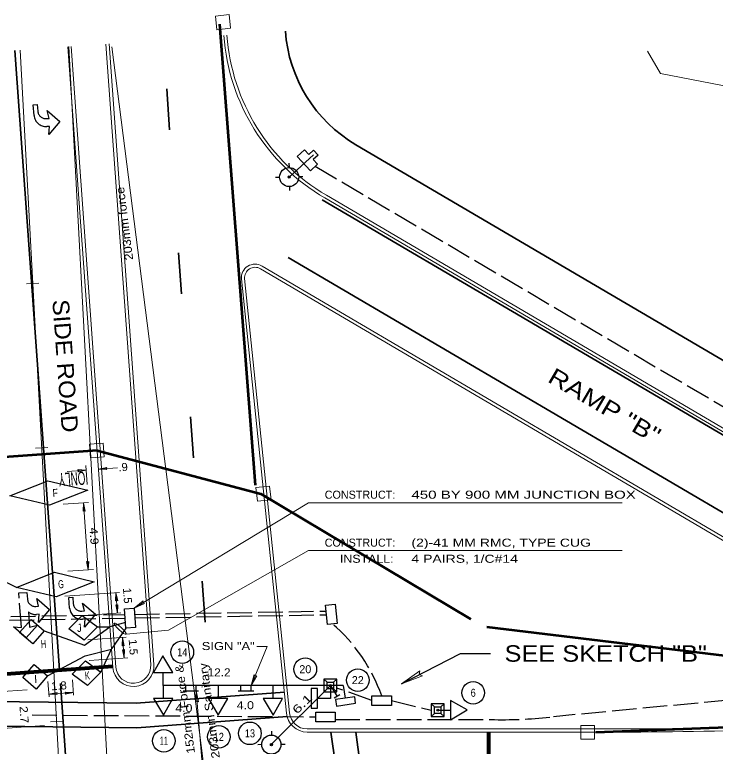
# Model space of a CAD drawing. Extents: x 168203 to 169864, y 223196 to 223870.
# Drawn here: x 168345.6 to 168396.8, y 223652.4 to 223705.8 of the extents above; entities that cross this region are included whole.
import ezdxf
from ezdxf.enums import TextEntityAlignment as Align

# ---------------------------------------------------------------- set-up
doc = ezdxf.new("R2010")
doc.units = 0
doc.header["$LTSCALE"] = 0.3
doc.header["$PDMODE"] = 32
doc.header["$PDSIZE"] = 0.15
doc.linetypes.add('LONG_DASH_SHORT_DASH', pattern=[9.9, 6, -1.2, 1.5, -1.2])
doc.linetypes.add('LONG_DASHED', pattern=[7.5, 6, -1.5])
for name, color, linetype, lineweight in [('1', 7, 'Continuous', 13), ('10', 7, 'Continuous', 13), ('23', 7, 'Continuous', 25), ('32', 7, 'Continuous', 25), ('36', 7, 'Continuous', 35), ('4', 7, 'Continuous', 25), ('6', 7, 'Continuous', 25), ('8', 7, 'Continuous', 25)]:
    doc.layers.add(name, color=color, linetype=linetype, lineweight=lineweight)

msp = doc.modelspace()

# ---------------------------------------------------------------- linework, layer by layer
at = {"layer": '1'}
for p, q in [((168349.7975, 223634.2675), (168346.0287, 223703.2124)), ((168352.8001, 223658.1888), (168349.528, 223703.4653)), ((168353.0296, 223658.2052), (168349.7575, 223703.4819)), ((168352.2908, 223703.665), (168355.5629, 223658.3883)), ((168352.5202, 223703.6815), (168355.7923, 223658.4049)), ((168417.1498, 223663.9927), (168368.3802, 223692.6319)), ((168417.0333, 223663.7944), (168368.2637, 223692.4336)), ((168363.5687, 223687.27), (168399.2919, 223666.2921)), ((168363.6851, 223687.4684), (168399.4139, 223666.4872)), ((168346.5111, 223686.1736), (168347.4098, 223686.2226)), ((168365.473, 223654.8595), (168362.1813, 223686.534)), ((168365.7018, 223654.8832), (168362.4101, 223686.5577)), ((168347.1644, 223674.1914), (168348.0631, 223674.2404)), ((168348.256, 223654.2212), (168349.1547, 223654.2702)), ((168389.7958, 223653.6976), (168366.9691, 223653.6976)), ((168389.7958, 223653.4676), (168366.9691, 223653.4676))]:
    msp.add_line(p, q, dxfattribs=at)
at = {"layer": '1', "lineweight": 35}
msp.add_line((168419.4337, 223667.6033), (168370.5425, 223696.3139), dxfattribs=at)
at = {"layer": '1'}
for points in [[(168360.2873, 223705.7061), (168361.2849, 223705.8098), (168361.3886, 223704.8122), (168360.391, 223704.7085)], [(168351.1029, 223674.483), (168352.1033, 223674.5553), (168352.1756, 223673.5549), (168351.1752, 223673.4826)], [(168363.2438, 223671.3005), (168364.2414, 223671.4042), (168364.3451, 223670.4066), (168363.3475, 223670.3029)], [(168386.9482, 223652.949), (168386.9482, 223653.952), (168387.9512, 223653.952), (168387.9512, 223652.949)]]:
    msp.add_lwpolyline(points, close=True, dxfattribs=at)
for centre, radius, start, end in [((168375.8594, 223705.3683), 15, 184.13349, 239.57703), ((168375.8594, 223705.3683), 14.77, 184.13349, 239.57703), ((168363.1787, 223686.6061), 1, 59.57703, 184.13349), ((168363.1787, 223686.6061), 0.77, 59.57703, 184.13349), ((168354.296, 223658.2969), 1.5, 184.13349, 4.13349), ((168354.296, 223658.2969), 1.27, 184.13349, 4.13349), ((168366.9691, 223654.9676), 1.5, 184.13349, 270.00005), ((168366.9691, 223654.9676), 1.27, 184.13349, 270.00005), ((168389.7956, 223953.4676), 299.77, 270.00005, 274.68735), ((168389.7956, 223953.4676), 300, 270.00005, 274.68735)]:
    msp.add_arc(centre, radius, start, end, dxfattribs=at)
at = {"layer": '1', "lineweight": 35}
msp.add_arc((168375.8594, 223705.3683), 10.5001, 184.13349, 239.57769, dxfattribs=at)
at = {"layer": '10'}
for p, q in [((168354.3616, 223662.5186), (168367.0853, 223670.2051)), ((168389.9644, 223670.2051), (168367.0853, 223670.2051)), ((168389.9644, 223666.7051), (168367.0853, 223666.7051))]:
    msp.add_line(p, q, dxfattribs=at)
at = {"layer": '10', "lineweight": 25}
for p, q in [((168373.8561, 223656.997), (168378.1708, 223659.2014)), ((168378.1708, 223659.2014), (168380.368, 223659.2014))]:
    msp.add_line(p, q, dxfattribs=at)
at = {"layer": '10'}
msp.add_lwpolyline([(168353.7695, 223660.6006), (168356.8513, 223660.8997), (168367.0853, 223666.7051)], dxfattribs=at)
for points in [[(168355.1091, 223662.8541), (168354.3616, 223662.5186), (168355.0017, 223663.0319), (168354.9881, 223662.8971)], [(168375.3951, 223657.56), (168373.8561, 223656.997), (168375.2059, 223657.9302), (168375.1597, 223657.663)]]:
    msp.add_lwpolyline(points, close=True, dxfattribs=at)
msp.add_ellipse((168353.3324, 223661.0127), major_axis=(-0.4371, 0.4121), ratio=0.187826, dxfattribs=at)
at = {"layer": '23', "lineweight": 53}
for p, q in [((168363.2123, 223671.494), (168360.5984, 223705.115)), ((168351.6566, 223674.0176), (168339.6878, 223673.1527)), ((168351.6566, 223674.0176), (168363.59, 223670.8389)), ((168363.59, 223670.8389), (168378.9117, 223661.7152)), ((168380.0972, 223661.1384), (168422.0981, 223656.1092)), ((168388.052, 223653.4671), (168412.6271, 223654.3671))]:
    msp.add_line(p, q, dxfattribs=at)
at = {"layer": '23', "lineweight": 13}
for p, q in [((168357.586, 223554.132), (168349.5897, 223703.4835)), ((168359.4003, 223651.3453), (168352.7333, 223703.4586))]:
    msp.add_line(p, q, dxfattribs=at)
msp.add_lwpolyline([(168391.8032, 223703.15), (168392.7497, 223701.5053), (168408.4668, 223698.4649)], dxfattribs=at)
at = {"layer": '32'}
for p, q in [((168367.4388, 223695.578), (168365.6659, 223693.9605)), ((168356.4781, 223656.8676), (168356.4781, 223657.8074)), ((168368.6781, 223656.8676), (168356.4781, 223656.8676)), ((168356.4781, 223656.8676), (168356.4781, 223655.9278)), ((168358.1165, 223656.4839), (168358.1165, 223656.8634)), ((168358.8755, 223656.4839), (168358.8755, 223656.8634)), ((168360.4781, 223656.8676), (168360.4781, 223655.9278)), ((168362.1365, 223656.4888), (168362.1365, 223656.8683)), ((168362.8955, 223656.4888), (168362.8955, 223656.8683)), ((168368.6781, 223656.8676), (168364.3648, 223652.5542)), ((168364.4781, 223656.8676), (168364.4781, 223655.9278)), ((168368.6781, 223656.8676), (168368.6781, 223655.9278)), ((168369.6179, 223656.8676), (168368.6781, 223656.8676)), ((168368.6781, 223656.8676), (168369.1665, 223656.0647)), ((168369.6179, 223656.8676), (168369.7512, 223655.9373)), ((168357.9267, 223656.4839), (168359.0562, 223656.4839)), ((168361.9467, 223656.4888), (168363.0762, 223656.4888)), ((168368.6781, 223655.9278), (168367.7383, 223655.9278)), ((168369.3672, 223656.1867), (168368.958, 223655.9379)), ((168376.5061, 223655.0676), (168377.4459, 223655.0676))]:
    msp.add_line(p, q, dxfattribs=at)
at = {"layer": '32', "lineweight": 13}
for p in [(168362.8955, 223656.8683), (168363.3021, 223659.7147)]:
    msp.add_line(p, (168364.0608, 223659.7147), dxfattribs=at)
at = {"layer": '32'}
for points in [[(168356.46, 223659.0272), (168355.7733, 223657.8074), (168356.4781, 223657.8074), (168357.1829, 223657.8074)], [(168367.2685, 223656.6417), (168367.2685, 223655.223), (168367.7383, 223655.223), (168367.7383, 223656.6417)], [(168356.4962, 223654.708), (168357.1829, 223655.9278), (168356.4781, 223655.9278), (168355.7733, 223655.9278)], [(168360.4962, 223654.708), (168361.1829, 223655.9278), (168360.4781, 223655.9278), (168359.7733, 223655.9278)], [(168364.4962, 223654.708), (168365.1829, 223655.9278), (168364.4781, 223655.9278), (168363.7733, 223655.9278)], [(168369.1112, 223655.371), (168370.5155, 223655.5722), (168370.4489, 223656.0373), (168369.0445, 223655.836)], [(168378.6657, 223655.0857), (168377.4459, 223655.7724), (168377.4459, 223655.0676), (168377.4459, 223654.3628)]]:
    msp.add_lwpolyline(points, close=True, dxfattribs=at)
at = {"layer": '32', "lineweight": 13}
for points in [[(168363.2956, 223657.5833), (168362.8955, 223656.8683), (168363.1033, 223657.662), (168363.1728, 223657.5456)], [(168358.8429, 223655.6652), (168358.8755, 223656.4839), (168359.05, 223655.6822), (168358.9353, 223655.7544)]]:
    msp.add_lwpolyline(points, close=True, dxfattribs=at)
msp.add_lwpolyline([(168358.5538, 223651.1547), (168359.3125, 223651.1547), (168358.8755, 223656.4839)], dxfattribs=at)
at = {"layer": '32'}
for centre in [(168357.8675, 223659.2956), (168366.8425, 223658.0542), (168370.6726, 223657.2577), (168379.0954, 223656.3366), (168362.8039, 223653.376), (168356.52, 223652.8356), (168360.5298, 223653.1218)]:
    msp.add_circle(centre, 0.8236, dxfattribs=at)
at = {"layer": '36'}
for p, q in [((168348.9037, 223658.0067), (168345.6389, 223703.1842)), ((168356.7281, 223700.3938), (168356.9443, 223697.4016)), ((168368.071, 223692.3059), (168402.7689, 223671.93)), ((168357.5931, 223688.425), (168357.8093, 223685.4328)), ((168365.5999, 223688.0978), (168400.2978, 223667.7219)), ((168358.4581, 223676.4562), (168358.6743, 223673.464)), ((168359.323, 223664.4874), (168359.5393, 223661.4952)), ((168349.5082, 223649.6433), (168348.9759, 223657.0092)), ((168354.5482, 223653.7832), (168365.5163, 223654.5943)), ((168331.8751, 223654.0405), (168354.5482, 223653.7832)), ((168374.0279, 223615.7265), (168368.7066, 223653.4676)), ((168375.8367, 223615.7899), (168370.5243, 223653.4676))]:
    msp.add_line(p, q, dxfattribs=at)
at = {"layer": '36', "lineweight": 80}
for p, q in [((168336.8478, 223657.135), (168352.7935, 223658.2879)), ((168380.2469, 223634.5676), (168380.2468, 223653.4676))]:
    msp.add_line(p, q, dxfattribs=at)
at = {"layer": '36', "linetype": 'LONG_DASH_SHORT_DASH', "lineweight": 25}
for points in [[(168347.0511, 223698.4569), (168346.9949, 223699.2352), (168347.2867, 223699.2563), (168347.3219, 223698.7699)], [(168347.9477, 223698.2284), (168348.1423, 223698.2425), (168348.0029, 223698.8191), (168348.9417, 223698.0069), (168348.1295, 223697.0681), (168348.1845, 223697.6588), (168347.9899, 223697.6447)], [(168346.635, 223662.2303), (168346.7145, 223661.1318), (168347.2911, 223661.2712), (168346.4789, 223660.3324), (168345.5401, 223661.1446), (168346.1308, 223661.0896), (168345.9479, 223663.6189), (168346.5316, 223663.6611), (168346.5668, 223663.1746)], [(168347.1926, 223662.6332), (168347.3872, 223662.6472), (168347.2478, 223663.2239)], [(168347.2478, 223663.2239), (168348.1866, 223662.4117), (168347.3744, 223661.4728), (168347.4294, 223662.0636), (168347.2348, 223662.0495)], [(168349.6464, 223662.519), (168349.5902, 223663.2973), (168349.882, 223663.3184), (168349.9172, 223662.832)], [(168350.543, 223662.2905), (168350.7376, 223662.3046), (168350.5982, 223662.8812), (168351.537, 223662.069), (168350.7248, 223661.1302), (168350.7798, 223661.7209), (168350.5852, 223661.7068)]]:
    msp.add_lwpolyline(points, dxfattribs=at)
at = {"layer": '36'}
msp.add_lwpolyline([(168335.3225, 223655.8015), (168354.4921, 223655.584), (168365.3145, 223656.3843)], dxfattribs=at)
at = {"layer": '36', "linetype": 'LONG_DASH_SHORT_DASH', "lineweight": 25}
for centre, radius, start in [((168347.9267, 223698.5203), 0.8778, 184.13538), ((168347.9056, 223698.8121), 0.5852, 184.13538), ((168347.1505, 223663.2169), 0.5852, 184.13538), ((168350.5009, 223662.8742), 0.5852, 184.13538), ((168347.1716, 223662.925), 0.8778, 232.32592), ((168350.522, 223662.5824), 0.8778, 184.13538)]:
    msp.add_arc(centre, radius, start, 274.13538, dxfattribs=at)
at = {"layer": '4'}
for p, q in [((168368.2037, 223657.3375), (168368.4387, 223657.1025)), ((168369.1435, 223657.3375), (168368.9085, 223657.1025)), ((168368.2037, 223656.3977), (168368.4387, 223656.6327)), ((168369.1435, 223656.3977), (168368.9085, 223656.6327)), ((168376.0317, 223655.5375), (168376.2667, 223655.3025)), ((168376.9715, 223655.5375), (168376.7365, 223655.3025)), ((168376.0317, 223654.5977), (168376.2667, 223654.8327)), ((168376.9715, 223654.5977), (168376.7365, 223654.8327))]:
    msp.add_line(p, q, dxfattribs=at)
for points in [[(168368.2037, 223657.3375), (168368.2037, 223656.3977), (168369.1435, 223656.3977), (168369.1435, 223657.3375)], [(168368.4387, 223657.1025), (168368.9085, 223657.1025), (168368.9085, 223656.6327), (168368.4387, 223656.6327)], [(168376.0317, 223655.5375), (168376.0317, 223654.5977), (168376.9715, 223654.5977), (168376.9715, 223655.5375)], [(168376.2667, 223655.3025), (168376.7365, 223655.3025), (168376.7365, 223654.8327), (168376.2667, 223654.8327)]]:
    msp.add_lwpolyline(points, close=True, dxfattribs=at)
for p in [(168368.6826, 223656.8676), (168376.5106, 223655.0676)]:
    msp.add_point(p, dxfattribs=at)
at = {"layer": '6', "linetype": 'LONG_DASHED'}
for p, q in [((168367.5642, 223694.7428), (168407.4794, 223671.2335)), ((168354.395, 223662.0561), (168368.3631, 223662.2946)), ((168338.522, 223661.5206), (168353.6992, 223661.7798)), ((168338.6143, 223661.7866), (168353.6802, 223662.0439)), ((168354.4141, 223661.7921), (168368.3905, 223662.0308)), ((168353.7213, 223661.474), (168352.5856, 223661.1565)), ((168353.7518, 223661.0521), (168352.7043, 223659.5146)), ((168371.7071, 223655.7676), (168369.1435, 223656.6774)), ((168406.6999, 223656.6401), (168384.9476, 223654.5887)), ((168373.1258, 223655.7676), (168376.0317, 223655.0676)), ((168346.9068, 223654.718), (168367.6027, 223654.5745)), ((168369.0214, 223654.3768), (168380.6473, 223654.3768))]:
    msp.add_line(p, q, dxfattribs=at)
at = {"layer": '6', "lineweight": 13}
for p, q in [((168350.934, 223671.5245), (168350.834, 223672.9104)), ((168350.8575, 223672.5844), (168349.4622, 223672.4836)), ((168353.1504, 223672.75), (168351.7551, 223672.6492)), ((168351.0284, 223670.2182), (168349.1684, 223670.0838)), ((168351.0081, 223665.304), (168350.655, 223670.1912)), ((168351.3816, 223665.331), (168349.5216, 223665.1966)), ((168353.2748, 223663.6634), (168349.2948, 223663.3756)), ((168353.1377, 223662.1496), (168353.0296, 223663.6457)), ((168353.383, 223662.1673), (168350.9998, 223661.995)), ((168353.7814, 223660.3914), (168350.9703, 223660.1882)), ((168353.6209, 223658.8758), (168353.5128, 223660.372)), ((168353.8895, 223658.8952), (168351.0784, 223658.6921)), ((168349.9391, 223656.1602), (168349.8577, 223657.2856)), ((168348.1443, 223656.0303), (168348.0629, 223657.1557)), ((168346.5587, 223656.5608), (168343.8831, 223656.3674)), ((168349.9248, 223656.3583), (168348.13, 223656.2288)), ((168347.8176, 223653.9523), (168341.1099, 223653.4676))]:
    msp.add_line(p, q, dxfattribs=at)
at = {"layer": '6'}
for p, q in [((168345.7614, 223664.0228), (168340.154, 223666.695)), ((168351.6844, 223661.1422), (168352.5856, 223661.1565)), ((168351.9222, 223657.8508), (168352.7043, 223659.5146))]:
    msp.add_line(p, q, dxfattribs=at)
for points in [[(168366.7862, 223695.9419), (168367.1038, 223695.5957), (168367.4501, 223695.9132), (168367.7738, 223695.5602), (168367.4276, 223695.2428), (168367.739, 223694.9031), (168367.2129, 223694.4206), (168366.2601, 223695.4594)], [(168345.2785, 223670.7052), (168348.0562, 223671.8082), (168350.9636, 223671.1158), (168348.186, 223670.0128)], [(168345.7614, 223664.0228), (168348.5391, 223665.1258), (168351.4465, 223664.4334), (168348.6689, 223663.3304)], [(168369.1738, 223661.399), (168368.4638, 223661.3252), (168368.3172, 223662.7363), (168369.0272, 223662.8101)], [(168354.4638, 223661.1036), (168353.7518, 223661.0521), (168353.6496, 223662.4671), (168354.3616, 223662.5186)], [(168345.9998, 223660.7313), (168346.8325, 223661.6938), (168347.7951, 223660.861), (168346.9623, 223659.8984)], [(168349.5899, 223660.9909), (168350.5722, 223661.9642), (168351.6844, 223661.1422), (168350.702, 223660.1688)], [(168346.2376, 223657.4401), (168347.0703, 223658.4026), (168348.0329, 223657.5698), (168347.2001, 223656.6072)], [(168349.8277, 223657.6995), (168350.81, 223658.6728), (168351.9222, 223657.8508), (168350.9398, 223656.8774)], [(168371.7071, 223655.4107), (168371.7071, 223656.1245), (168373.1258, 223656.1245), (168373.1258, 223655.4107)], [(168367.6027, 223654.2176), (168367.6027, 223654.9314), (168369.0214, 223654.9314), (168369.0214, 223654.2176)]]:
    msp.add_lwpolyline(points, close=True, dxfattribs=at)
at = {"layer": '6', "lineweight": 13}
for points in [[(168352.3688, 223672.6188), (168351.7551, 223672.6492), (168352.3577, 223672.7742), (168352.3026, 223672.6887)], [(168350.2438, 223672.6148), (168350.8575, 223672.5844), (168350.2549, 223672.4594), (168350.31, 223672.5449)], [(168350.6246, 223669.5775), (168350.655, 223670.1912), (168350.78, 223669.5886), (168350.6945, 223669.6437)], [(168351.0385, 223665.9177), (168351.0081, 223665.304), (168350.8831, 223665.9066), (168350.9686, 223665.8515)], [(168352.9992, 223663.032), (168353.0296, 223663.6457), (168353.1546, 223663.0431), (168353.0691, 223663.0982)], [(168353.1681, 223662.7633), (168353.1377, 223662.1496), (168353.0127, 223662.7522), (168353.0982, 223662.6971)], [(168353.4824, 223659.7583), (168353.5128, 223660.372), (168353.6378, 223659.7694), (168353.5523, 223659.8245)], [(168353.6513, 223659.4895), (168353.6209, 223658.8758), (168353.4959, 223659.4784), (168353.5814, 223659.4233)], [(168348.7437, 223656.1984), (168348.13, 223656.2288), (168348.7326, 223656.3538), (168348.6775, 223656.2683)], [(168349.3111, 223656.3887), (168349.9248, 223656.3583), (168349.3222, 223656.2333), (168349.3773, 223656.3188)]]:
    msp.add_lwpolyline(points, close=True, dxfattribs=at)
at = {"layer": '6'}
for points in [[(168347.7951, 223660.861), (168350.7276, 223659.8149), (168352.5856, 223661.1565)], [(168348.0329, 223657.5698), (168350.7848, 223659.021), (168352.7043, 223659.5146)]]:
    msp.add_lwpolyline(points, dxfattribs=at)
at = {"layer": '6', "linetype": 'LONG_DASHED'}
for centre, radius, start, end in [((168360.8437, 223652.0298), 12.2757, 19.48491, 49.48384), ((168381.2447, 223685.9948), 31.6236, 268.91761, 276.7244)]:
    msp.add_arc(centre, radius, start, end, dxfattribs=at)
at = {"layer": '8'}
for p, q in [((168365.6488, 223694.9731), (168365.6552, 223694.6538)), ((168364.6788, 223693.9504), (168364.9661, 223693.9625)), ((168366.3586, 223693.9903), (168366.6718, 223693.9902)), ((168365.683, 223693.261), (168365.6952, 223692.9738)), ((168364.3744, 223653.5413), (168364.3808, 223653.2538)), ((168363.6651, 223652.551), (168363.3777, 223652.5446)), ((168365.3776, 223652.551), (168365.0581, 223652.551))]:
    msp.add_line(p, q, dxfattribs=at)
for centre in [(168365.6659, 223693.9605), (168364.3648, 223652.5542)]:
    msp.add_circle(centre, 0.6965, dxfattribs=at)
for p in [(168365.669, 223693.9637), (168364.368, 223652.551)]:
    msp.add_point(p, dxfattribs=at)

# ---------------------------------------------------------------- texts
at = {"layer": '1'}
for s, rotation, width, p in [('SIDE ROAD', 274.133, 1.1, (168348.7371, 223680.1369)), ('RAMP "B"', 329.577, 1.25, (168388.3819, 223676.7554))]:
    msp.add_text(s, height=1.202, rotation=rotation, dxfattribs=dict(at, width=width)).set_placement(p, align=Align.CENTER)
at = {"layer": '10'}
for p in [(168368.26, 223670.4943), (168368.26, 223666.9943)]:
    msp.add_text('CONSTRUCT:', height=0.5873, dxfattribs=at).set_placement(p)
for s, width, p in [('450 BY 900 MM JUNCTION BOX           ', 1.4, (168374.5853, 223670.4943)), ('(2)-41 MM RMC, TYPE CUG              ', 1.3, (168374.5853, 223666.9943)), ('4 PAIRS, 1/C#14                      ', 1.3, (168374.5853, 223665.8196))]:
    msp.add_text(s, height=0.5873, dxfattribs=dict(at, width=width)).set_placement(p)
at = {"layer": '10', "width": 1.15}
msp.add_text('INSTALL:', height=0.5873, dxfattribs=at).set_placement((168373.2872, 223665.8196), align=Align.RIGHT)
msp.add_text('SEE SKETCH "B"', height=1.202, dxfattribs=at).set_placement((168388.7656, 223658.6005), align=Align.CENTER)
at = {"layer": '23'}
for s, rotation, width, p in [('203mm force', 97.198, 1.15, (168353.9495, 223690.5999)), ('152mm Force & ', 97.692, 1.15, (168358.3408, 223655.3191)), ('203mm Sanitary', 97.692, 1.2, (168360.1428, 223655.0662))]:
    msp.add_text(s, height=0.6, rotation=rotation, dxfattribs=dict(at, width=width)).set_placement(p, align=Align.CENTER)
at = {"layer": '32'}
for s, width, p in [('SIGN "A"', 1.2, (168361.2205, 223659.4509)), ('14', 0.85, (168357.8675, 223659.002)), ('12.2', 1.1, (168360.5519, 223657.5294)), ('6', 0.85, (168379.0954, 223656.043)), ('4.0', 1.15, (168362.4698, 223655.1354)), ('4.0', 1.15, (168357.9811, 223654.9306)), ('13', 0.85, (168362.8039, 223653.0824)), ('11', 0.7, (168356.52, 223652.542)), ('12', 0.85, (168360.5298, 223652.8282))]:
    msp.add_text(s, height=0.5873, dxfattribs=dict(at, width=width)).set_placement(p, align=Align.CENTER)
for s, p in [('20', (168366.8426, 223657.7606)), ('22', (168370.6727, 223656.9641))]:
    msp.add_text(s, height=0.5873, dxfattribs=at).set_placement(p, align=Align.CENTER)
at = {"layer": '32', "width": 1.5}
msp.add_text('6.1', height=0.5873, rotation=45.001, dxfattribs=at).set_placement((168366.8232, 223655.3188), align=Align.CENTER)
at = {"layer": '36', "width": 0.55}
msp.add_text('ONLY', height=0.9715, rotation=183.898, dxfattribs=at).set_placement((168349.7856, 223672.4202), align=Align.CENTER)
at = {"layer": '6'}
for s, rotation, width, p in [('.9', 4.134, 1.05, (168353.567, 223672.5045)), ('F', 4.133, 0.8, (168348.6145, 223670.623)), ('4.9', 274.134, 1.15, (168351.1406, 223667.7482)), ('G', 4.133, 0.65, (168349.0347, 223663.9642)), ('1.5', 274.132, 1.05, (168353.5776, 223663.3972)), ('J', 4.133, 0.85, (168350.3729, 223660.7776)), ('H', 4.133, 0.65, (168347.7629, 223659.5998)), ('1.5', 274.132, 1.05, (168353.9967, 223659.6493)), ('K', 4.133, 0.7, (168350.9616, 223657.305)), ('1.8', 4.132, 1.05, (168348.8834, 223656.5553)), ('2.7', 274.132, 1.15, (168346.0351, 223654.7166))]:
    msp.add_text(s, height=0.5873, rotation=rotation, dxfattribs=dict(at, width=width)).set_placement(p, align=Align.CENTER)
msp.add_text('I', height=0.5873, rotation=4.133, dxfattribs=at).set_placement((168347.1897, 223657.0443), align=Align.CENTER)

doc.saveas('drawing.dxf')
